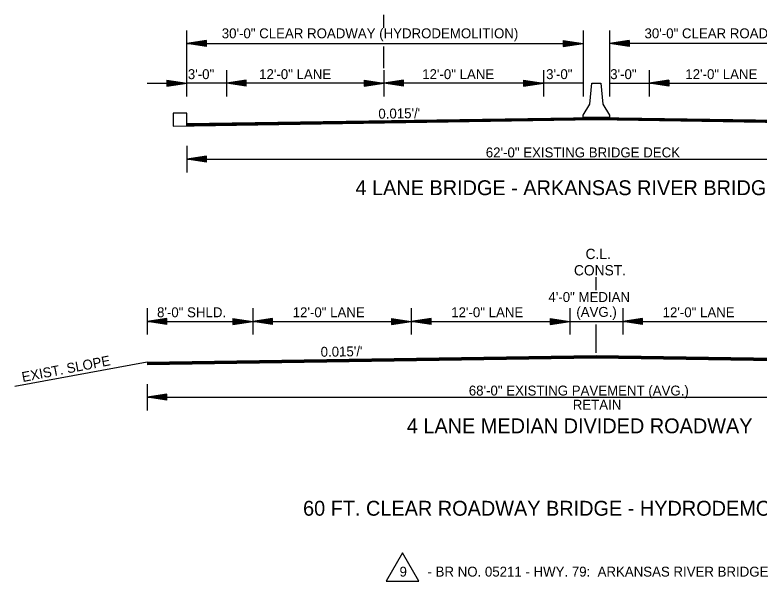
# Model space of a CAD drawing. Extents: x 549600 to 1930787, y -1955432 to 596640.
# Drawn here: x 551111 to 551675, y -1947605 to -1947177 of the extents above; entities that cross this region are included whole.
import ezdxf

# ---------------------------------------------------------------- set-up
doc = ezdxf.new("R2010")
doc.units = 0
for name, color, linetype in [('Default', 7, 'Continuous'), ('R_Border', 7, 'Continuous'), ('S_AREA_CALC', 7, 'Continuous')]:
    doc.layers.add(name, color=color, linetype=linetype)

# ---------------------------------------------------------------- blocks, each defined once
blk = doc.blocks.new('MedBarrier')
at = {"layer": 'Default'}
blk.add_lwpolyline([(-9.99, 0), (-9.91, 1.67), (-4.99, 10), (-3.32, 25.83), (3.32, 25.83), (4.99, 10), (9.91, 1.67), (9.99, 0)], close=True, dxfattribs=at)

msp = doc.modelspace()

# ---------------------------------------------------------------- linework, layer by layer
at = {"layer": 'R_Border'}
for p, q in [((551211.35, -1947228.55), (551241.35, -1947228.55)), ((551392.2, -1947605.21), (551417, -1947605.21))]:
    msp.add_line(p, q, dxfattribs=at)
for points in [[(551241.35, -1947260.53), (551241.35, -1947251.09), (551231.18, -1947251.09), (551231.18, -1947260.88)], [(551417, -1947605.21), (551404.6, -1947583.73), (551392.2, -1947605.21)]]:
    msp.add_lwpolyline(points, dxfattribs=at)
at = {"layer": 'S_AREA_CALC'}
for p, q in [((551390.55, -1947186.68), (551390.55, -1947176.81)), ((551241.35, -1947238.55), (551241.35, -1947188.55)), ((551541.35, -1947188.55), (551541.35, -1947238.55)), ((551561.35, -1947188.55), (551561.35, -1947238.55)), ((551256.35, -1947196.3), (551241.35, -1947198.55)), ((551256.35, -1947196.67), (551243.85, -1947198.55)), ((551256.35, -1947197.05), (551246.43, -1947198.55)), ((551256.35, -1947197.43), (551248.93, -1947198.55)), ((551256.35, -1947197.81), (551251.47, -1947198.55)), ((551256.35, -1947200.8), (551256.35, -1947196.3)), ((551526.35, -1947196.3), (551541.35, -1947198.55)), ((551526.35, -1947196.3), (551526.35, -1947200.8)), ((551526.35, -1947196.67), (551538.84, -1947198.55)), ((551526.35, -1947197.05), (551536.26, -1947198.55)), ((551526.35, -1947197.43), (551533.76, -1947198.55)), ((551526.35, -1947197.82), (551531.22, -1947198.55)), ((551576.35, -1947196.3), (551561.35, -1947198.55)), ((551576.35, -1947196.67), (551563.85, -1947198.55)), ((551576.35, -1947197.05), (551566.43, -1947198.55)), ((551576.35, -1947197.43), (551568.93, -1947198.55)), ((551576.35, -1947197.82), (551571.47, -1947198.55)), ((551576.35, -1947196.3), (551576.35, -1947200.8)), ((551241.35, -1947198.55), (551541.35, -1947198.55)), ((551256.35, -1947200.8), (551241.35, -1947198.55)), ((551256.35, -1947200.42), (551243.85, -1947198.55)), ((551256.35, -1947200.04), (551246.43, -1947198.55)), ((551256.35, -1947199.66), (551248.93, -1947198.55)), ((551256.35, -1947199.27), (551251.47, -1947198.55)), ((551256.35, -1947198.19), (551253.98, -1947198.55)), ((551256.35, -1947198.9), (551253.98, -1947198.55)), ((551390.55, -1947217.21), (551390.55, -1947200.71)), ((551526.35, -1947198.19), (551528.72, -1947198.55)), ((551526.35, -1947200.8), (551541.35, -1947198.55)), ((551526.35, -1947199.28), (551531.22, -1947198.55)), ((551526.35, -1947200.04), (551536.26, -1947198.55)), ((551526.35, -1947200.42), (551538.84, -1947198.55)), ((551526.35, -1947199.66), (551533.76, -1947198.55)), ((551526.35, -1947198.9), (551528.72, -1947198.55)), ((551861.35, -1947198.55), (551561.35, -1947198.55)), ((551576.35, -1947200.8), (551561.35, -1947198.55)), ((551576.35, -1947200.42), (551563.85, -1947198.55)), ((551576.35, -1947200.04), (551566.43, -1947198.55)), ((551576.35, -1947199.66), (551568.93, -1947198.55)), ((551576.35, -1947199.28), (551571.47, -1947198.55)), ((551576.35, -1947198.19), (551573.98, -1947198.55)), ((551576.35, -1947198.9), (551573.98, -1947198.55)), ((551271.35, -1947218.55), (551271.35, -1947238.55)), ((551390.55, -1947218.55), (551390.55, -1947238.55)), ((551511.35, -1947218.55), (551511.35, -1947238.55)), ((551591.35, -1947218.55), (551591.35, -1947238.55)), ((551226.35, -1947226.3), (551241.35, -1947228.55)), ((551226.35, -1947226.3), (551226.35, -1947230.8)), ((551286.35, -1947226.3), (551271.35, -1947228.55)), ((551286.35, -1947230.8), (551286.35, -1947226.3)), ((551375.55, -1947226.3), (551390.55, -1947228.55)), ((551375.55, -1947226.3), (551375.55, -1947230.8)), ((551405.55, -1947226.3), (551390.55, -1947228.55)), ((551405.55, -1947230.8), (551405.55, -1947226.3)), ((551496.35, -1947226.3), (551511.35, -1947228.55)), ((551496.35, -1947226.3), (551496.35, -1947230.8)), ((551606.35, -1947226.3), (551591.35, -1947228.55)), ((551606.35, -1947226.3), (551606.35, -1947230.8)), ((551226.35, -1947226.67), (551238.84, -1947228.55)), ((551226.35, -1947227.05), (551236.26, -1947228.55)), ((551226.35, -1947227.43), (551233.76, -1947228.55)), ((551226.35, -1947227.82), (551231.22, -1947228.55)), ((551226.35, -1947228.19), (551228.72, -1947228.55)), ((551226.35, -1947230.8), (551241.35, -1947228.55)), ((551226.35, -1947229.28), (551231.22, -1947228.55)), ((551226.35, -1947230.04), (551236.26, -1947228.55)), ((551226.35, -1947230.42), (551238.84, -1947228.55)), ((551226.35, -1947229.66), (551233.76, -1947228.55)), ((551226.35, -1947228.9), (551228.72, -1947228.55)), ((551541.35, -1947228.55), (551241.35, -1947228.55)), ((551286.35, -1947230.8), (551271.35, -1947228.55)), ((551286.35, -1947226.67), (551273.85, -1947228.55)), ((551286.35, -1947230.42), (551273.85, -1947228.55)), ((551286.35, -1947227.05), (551276.43, -1947228.55)), ((551286.35, -1947230.04), (551276.43, -1947228.55)), ((551286.35, -1947227.43), (551278.93, -1947228.55)), ((551286.35, -1947229.66), (551278.93, -1947228.55)), ((551286.35, -1947227.81), (551281.47, -1947228.55)), ((551286.35, -1947229.27), (551281.47, -1947228.55)), ((551286.35, -1947228.19), (551283.98, -1947228.55)), ((551286.35, -1947228.9), (551283.98, -1947228.55)), ((551375.55, -1947226.67), (551388.05, -1947228.55)), ((551375.55, -1947227.05), (551385.47, -1947228.55)), ((551375.55, -1947227.43), (551382.97, -1947228.55)), ((551375.55, -1947227.82), (551380.43, -1947228.55)), ((551375.55, -1947228.19), (551377.92, -1947228.55)), ((551375.55, -1947230.8), (551390.55, -1947228.55)), ((551375.55, -1947229.28), (551380.43, -1947228.55)), ((551375.55, -1947230.04), (551385.47, -1947228.55)), ((551375.55, -1947230.42), (551388.05, -1947228.55)), ((551375.55, -1947229.66), (551382.97, -1947228.55)), ((551375.55, -1947228.9), (551377.92, -1947228.55)), ((551405.55, -1947230.8), (551390.55, -1947228.55)), ((551405.55, -1947226.67), (551393.06, -1947228.55)), ((551405.55, -1947230.42), (551393.06, -1947228.55)), ((551405.55, -1947227.05), (551395.64, -1947228.55)), ((551405.55, -1947230.04), (551395.64, -1947228.55)), ((551405.55, -1947227.43), (551398.14, -1947228.55)), ((551405.55, -1947229.66), (551398.14, -1947228.55)), ((551405.55, -1947227.81), (551400.68, -1947228.55)), ((551405.55, -1947229.27), (551400.68, -1947228.55)), ((551405.55, -1947228.19), (551403.18, -1947228.55)), ((551405.55, -1947228.9), (551403.18, -1947228.55)), ((551496.35, -1947226.67), (551508.84, -1947228.55)), ((551496.35, -1947227.05), (551506.26, -1947228.55)), ((551496.35, -1947227.43), (551503.76, -1947228.55)), ((551496.35, -1947227.82), (551501.22, -1947228.55)), ((551496.35, -1947228.19), (551498.72, -1947228.55)), ((551496.35, -1947230.8), (551511.35, -1947228.55)), ((551496.35, -1947229.28), (551501.22, -1947228.55)), ((551496.35, -1947230.04), (551506.26, -1947228.55)), ((551496.35, -1947230.42), (551508.84, -1947228.55)), ((551496.35, -1947229.66), (551503.76, -1947228.55)), ((551496.35, -1947228.9), (551498.72, -1947228.55)), ((551561.35, -1947228.55), (551861.35, -1947228.55)), ((551606.35, -1947230.8), (551591.35, -1947228.55)), ((551606.35, -1947226.67), (551593.85, -1947228.55)), ((551606.35, -1947230.42), (551593.85, -1947228.55)), ((551606.35, -1947227.05), (551596.43, -1947228.55)), ((551606.35, -1947230.04), (551596.43, -1947228.55)), ((551606.35, -1947227.43), (551598.93, -1947228.55)), ((551606.35, -1947229.66), (551598.93, -1947228.55)), ((551606.35, -1947227.82), (551601.47, -1947228.55)), ((551606.35, -1947229.28), (551601.47, -1947228.55)), ((551606.35, -1947228.19), (551603.98, -1947228.55)), ((551606.35, -1947228.9), (551603.98, -1947228.55)), ((551241.35, -1947275.96), (551241.35, -1947295.96)), ((551256.35, -1947283.71), (551241.35, -1947285.96)), ((551241.35, -1947285.96), (551861.35, -1947285.96)), ((551256.35, -1947288.21), (551241.35, -1947285.96)), ((551256.35, -1947284.08), (551243.85, -1947285.96)), ((551256.35, -1947287.83), (551243.85, -1947285.96)), ((551256.35, -1947284.46), (551246.43, -1947285.96)), ((551256.35, -1947287.45), (551246.43, -1947285.96)), ((551256.35, -1947284.84), (551248.93, -1947285.96)), ((551256.35, -1947287.07), (551248.93, -1947285.96)), ((551256.35, -1947285.22), (551251.47, -1947285.96)), ((551256.35, -1947286.68), (551251.47, -1947285.96)), ((551256.35, -1947285.6), (551253.98, -1947285.96)), ((551256.35, -1947286.31), (551253.98, -1947285.96)), ((551256.35, -1947288.21), (551256.35, -1947283.71)), ((551551.35, -1947385.09), (551551.35, -1947375.22)), ((551211.35, -1947398.7), (551211.35, -1947418.7)), ((551291.35, -1947398.7), (551291.35, -1947418.7)), ((551411.35, -1947398.7), (551411.35, -1947418.7)), ((551531.35, -1947398.7), (551531.35, -1947418.7)), ((551571.35, -1947398.7), (551571.35, -1947418.7)), ((551226.35, -1947406.45), (551211.35, -1947408.7)), ((551226.35, -1947410.95), (551226.35, -1947406.45)), ((551276.35, -1947406.45), (551291.35, -1947408.7)), ((551276.35, -1947406.45), (551276.35, -1947410.95)), ((551306.35, -1947406.45), (551291.35, -1947408.7)), ((551306.35, -1947410.95), (551306.35, -1947406.45)), ((551396.35, -1947406.45), (551411.35, -1947408.7)), ((551396.35, -1947406.45), (551396.35, -1947410.95)), ((551426.35, -1947406.45), (551411.35, -1947408.7)), ((551426.35, -1947410.95), (551426.35, -1947406.45)), ((551516.35, -1947406.45), (551531.35, -1947408.7)), ((551516.35, -1947406.45), (551516.35, -1947410.95)), ((551586.35, -1947406.45), (551571.35, -1947408.7)), ((551586.35, -1947410.95), (551586.35, -1947406.45)), ((551211.35, -1947408.7), (551891.35, -1947408.7)), ((551226.35, -1947410.95), (551211.35, -1947408.7)), ((551226.35, -1947406.82), (551213.85, -1947408.7)), ((551226.35, -1947410.57), (551213.85, -1947408.7)), ((551226.35, -1947407.21), (551216.43, -1947408.7)), ((551226.35, -1947410.19), (551216.43, -1947408.7)), ((551226.35, -1947407.58), (551218.93, -1947408.7)), ((551226.35, -1947409.82), (551218.93, -1947408.7)), ((551226.35, -1947407.96), (551221.47, -1947408.7)), ((551226.35, -1947409.43), (551221.47, -1947408.7)), ((551226.35, -1947408.35), (551223.98, -1947408.7)), ((551226.35, -1947409.05), (551223.98, -1947408.7)), ((551276.35, -1947406.82), (551288.84, -1947408.7)), ((551276.35, -1947407.21), (551286.26, -1947408.7)), ((551276.35, -1947407.58), (551283.76, -1947408.7)), ((551276.35, -1947407.97), (551281.22, -1947408.7)), ((551276.35, -1947408.35), (551278.72, -1947408.7)), ((551276.35, -1947410.95), (551291.35, -1947408.7)), ((551276.35, -1947409.43), (551281.22, -1947408.7)), ((551276.35, -1947410.19), (551286.26, -1947408.7)), ((551276.35, -1947410.57), (551288.84, -1947408.7)), ((551276.35, -1947409.82), (551283.76, -1947408.7)), ((551276.35, -1947409.05), (551278.72, -1947408.7)), ((551306.35, -1947410.95), (551291.35, -1947408.7)), ((551306.35, -1947406.82), (551293.85, -1947408.7)), ((551306.35, -1947410.57), (551293.85, -1947408.7)), ((551306.35, -1947407.21), (551296.43, -1947408.7)), ((551306.35, -1947410.19), (551296.43, -1947408.7)), ((551306.35, -1947407.58), (551298.93, -1947408.7)), ((551306.35, -1947409.82), (551298.93, -1947408.7)), ((551306.35, -1947407.96), (551301.47, -1947408.7)), ((551306.35, -1947409.43), (551301.47, -1947408.7)), ((551306.35, -1947408.35), (551303.98, -1947408.7)), ((551306.35, -1947409.05), (551303.98, -1947408.7)), ((551396.35, -1947406.82), (551408.84, -1947408.7)), ((551396.35, -1947407.21), (551406.26, -1947408.7)), ((551396.35, -1947407.58), (551403.76, -1947408.7)), ((551396.35, -1947407.97), (551401.22, -1947408.7)), ((551396.35, -1947408.35), (551398.72, -1947408.7)), ((551396.35, -1947410.95), (551411.35, -1947408.7)), ((551396.35, -1947409.43), (551401.22, -1947408.7)), ((551396.35, -1947410.19), (551406.26, -1947408.7)), ((551396.35, -1947410.57), (551408.84, -1947408.7)), ((551396.35, -1947409.82), (551403.76, -1947408.7)), ((551396.35, -1947409.05), (551398.72, -1947408.7)), ((551426.35, -1947410.95), (551411.35, -1947408.7)), ((551426.35, -1947406.82), (551413.85, -1947408.7)), ((551426.35, -1947410.57), (551413.85, -1947408.7)), ((551426.35, -1947407.21), (551416.43, -1947408.7)), ((551426.35, -1947410.19), (551416.43, -1947408.7)), ((551426.35, -1947407.58), (551418.93, -1947408.7)), ((551426.35, -1947409.82), (551418.93, -1947408.7)), ((551426.35, -1947407.96), (551421.47, -1947408.7)), ((551426.35, -1947409.43), (551421.47, -1947408.7)), ((551426.35, -1947408.35), (551423.98, -1947408.7)), ((551426.35, -1947409.05), (551423.98, -1947408.7)), ((551516.35, -1947406.82), (551528.84, -1947408.7)), ((551516.35, -1947407.21), (551526.26, -1947408.7)), ((551516.35, -1947407.58), (551523.76, -1947408.7)), ((551516.35, -1947407.97), (551521.22, -1947408.7)), ((551516.35, -1947408.35), (551518.72, -1947408.7)), ((551516.35, -1947410.95), (551531.35, -1947408.7)), ((551516.35, -1947409.43), (551521.22, -1947408.7)), ((551516.35, -1947410.19), (551526.26, -1947408.7)), ((551516.35, -1947410.57), (551528.84, -1947408.7)), ((551516.35, -1947409.82), (551523.76, -1947408.7)), ((551516.35, -1947409.05), (551518.72, -1947408.7)), ((551551.35, -1947432.54), (551551.35, -1947411.17)), ((551586.35, -1947410.95), (551571.35, -1947408.7)), ((551586.35, -1947406.82), (551573.85, -1947408.7)), ((551586.35, -1947410.57), (551573.85, -1947408.7)), ((551586.35, -1947407.21), (551576.43, -1947408.7)), ((551586.35, -1947410.19), (551576.43, -1947408.7)), ((551586.35, -1947407.58), (551578.93, -1947408.7)), ((551586.35, -1947409.82), (551578.93, -1947408.7)), ((551586.35, -1947407.96), (551581.47, -1947408.7)), ((551586.35, -1947409.43), (551581.47, -1947408.7)), ((551586.35, -1947408.35), (551583.98, -1947408.7)), ((551586.35, -1947409.05), (551583.98, -1947408.7)), ((551211.35, -1947439.63), (551111.28, -1947458.01)), ((551211.35, -1947456.11), (551211.35, -1947476.11)), ((551226.35, -1947463.86), (551211.35, -1947466.11)), ((551211.35, -1947466.11), (551891.35, -1947466.11)), ((551226.35, -1947468.36), (551211.35, -1947466.11)), ((551226.35, -1947464.23), (551213.85, -1947466.11)), ((551226.35, -1947467.98), (551213.85, -1947466.11)), ((551226.35, -1947464.62), (551216.43, -1947466.11)), ((551226.35, -1947467.6), (551216.43, -1947466.11)), ((551226.35, -1947464.99), (551218.93, -1947466.11)), ((551226.35, -1947467.23), (551218.93, -1947466.11)), ((551226.35, -1947465.37), (551221.47, -1947466.11)), ((551226.35, -1947466.84), (551221.47, -1947466.11)), ((551226.35, -1947465.76), (551223.98, -1947466.11)), ((551226.35, -1947466.46), (551223.98, -1947466.11)), ((551226.35, -1947468.36), (551226.35, -1947463.86))]:
    msp.add_line(p, q, dxfattribs=at)
for points in [[(551241.35, -1947259.03), (551551.35, -1947254.38), (551861.35, -1947259.03)], [(551231.18, -1947260.88), (551551.35, -1947256.08), (551871.51, -1947260.88)], [(551241.35, -1947259.33), (551551.35, -1947254.68), (551861.35, -1947259.33)], [(551241.35, -1947259.63), (551551.35, -1947254.98), (551861.35, -1947259.63)], [(551241.35, -1947259.93), (551551.35, -1947255.28), (551861.35, -1947259.93)], [(551241.35, -1947260.23), (551551.35, -1947255.58), (551861.35, -1947260.23)], [(551241.35, -1947260.53), (551551.35, -1947255.88), (551861.35, -1947260.53)], [(551211.35, -1947439.63), (551551.35, -1947434.53), (551891.35, -1947439.63)], [(551211.35, -1947439.93), (551551.35, -1947434.83), (551891.35, -1947439.93)], [(551211.35, -1947440.23), (551551.35, -1947435.13), (551891.35, -1947440.23)], [(551211.35, -1947440.53), (551551.35, -1947435.43), (551891.35, -1947440.53)], [(551211.35, -1947440.83), (551551.35, -1947435.73), (551891.35, -1947440.83)], [(551211.35, -1947441.13), (551551.35, -1947436.03), (551891.35, -1947441.13)], [(551211.35, -1947441.33), (551551.35, -1947436.23), (551891.35, -1947441.33)]]:
    msp.add_lwpolyline(points, dxfattribs=at)

# ---------------------------------------------------------------- block references
at = {"layer": 'S_AREA_CALC', "rotation": 0.0005105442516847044}
msp.add_blockref('MedBarrier', (551551.35, -1947254.38), dxfattribs=at)

# ---------------------------------------------------------------- texts
at = {"layer": 'R_Border'}
for s, height, p in [('30\'-0" CLEAR ROADWAY (HYDRODEMOLITION)', 7.5, (551267.86, -1947194.52)), ('30\'-0" CLEAR ROADWAY (HYDRODEMOLITION)', 7.5, (551587.86, -1947194.52)), ('60 FT. CLEAR ROADWAY BRIDGE - HYDRODEMOLITION', 11.25, (551329.4, -1947555.72)), ('9', 7.5, (551402.44, -1947601.8)), ('- BR NO. 05211 - HWY. 79:  ARKANSAS RIVER BRIDGE', 7.5, (551423.6, -1947601.8))]:
    msp.add_text(s, height=height, dxfattribs=at).set_placement(p)
at = {"layer": 'S_AREA_CALC'}
for s, height, p in [('3\'-0"', 7.5, (551242.19, -1947225.41)), ('12\'-0" LANE', 7.5, (551296.15, -1947225.41)), ('12\'-0" LANE', 7.5, (551419.57, -1947225.41)), ('3\'-0"', 7.5, (551513.36, -1947225.41)), ('3\'-0"', 7.5, (551561.87, -1947225.41)), ('12\'-0" LANE', 7.5, (551618.75, -1947225.41)), ('62\'-0" EXISTING BRIDGE DECK', 7.5, (551467.72, -1947284.63)), ('4 LANE BRIDGE - ARKANSAS RIVER BRIDGE', 11.25, (551369.06, -1947313.2)), ('C.L.', 7.8, (551543.24, -1947361.56)), ('CONST.', 7.8, (551534.46, -1947373.93)), ('4\'-0" MEDIAN', 7.5, (551515.12, -1947394.03)), ('8\'-0" SHLD.', 7.5, (551218.87, -1947405.56)), ('12\'-0" LANE', 7.5, (551321.55, -1947405.56)), ('12\'-0" LANE', 7.5, (551441.55, -1947405.56)), ('(AVG.)', 7.5, (551536.23, -1947405.28)), ('12\'-0" LANE', 7.5, (551601.55, -1947405.56)), ('68\'-0" EXISTING PAVEMENT (AVG.)', 7.5, (551454.85, -1947464.79)), ('RETAIN', 7.5, (551533.54, -1947475.51)), ('4 LANE MEDIAN DIVIDED ROADWAY', 11.25, (551407.95, -1947493.35))]:
    msp.add_text(s, height=height, dxfattribs=at).set_placement(p)
for s, rotation, p in [("0.015'/'", 0.8594, (551386.45, -1947255.35)), ("0.015'/'", 0.8594, (551342.76, -1947435.51)), ('EXIST. SLOPE', 10.8829, (551117.26, -1947454.63))]:
    msp.add_text(s, height=7.5, rotation=rotation, dxfattribs=at).set_placement(p)

doc.saveas('drawing.dxf')
